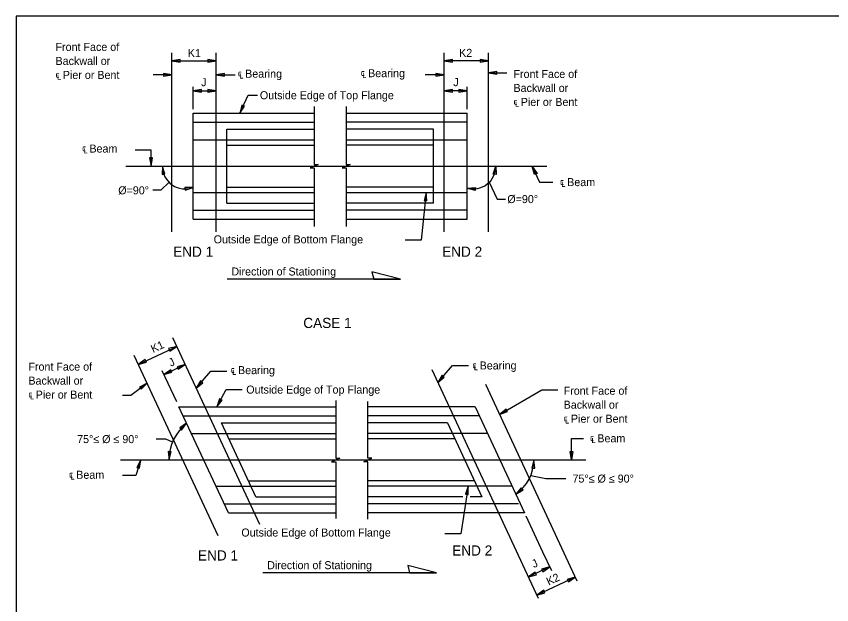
# Model space of a CAD drawing. Extents: x 120790.7 to 120844.8, y 120612.1 to 120653.6.
# Drawn here: x 120790.7 to 120806.1, y 120639.21 to 120650.31 of the extents above; entities that cross this region are included whole.
import ezdxf

# ---------------------------------------------------------------- set-up
doc = ezdxf.new("R2010")
doc.units = 0
for name, color, linetype in [('ActivePts-ConstElements', 7, 'Continuous'), ('AdhocPoint_dp', 7, 'Continuous'), ('Border', 7, 'Continuous'), ('Patterning', 7, 'Continuous'), ('PlotBorder_dp', 7, 'Continuous'), ('TextMisc', 7, 'Continuous')]:
    doc.layers.add(name, color=color, linetype=linetype)

# ---------------------------------------------------------------- blocks, each defined once
blk = doc.blocks.new('Terminator-Arrow')
at = {"layer": 'PlotBorder_dp'}
blk.add_lwpolyline([(0, 0), (-0.00041, 0.000069), (-0.00041, -0.000069)], close=True, dxfattribs=at)

msp = doc.modelspace()

# ---------------------------------------------------------------- linework, layer by layer
at = {"layer": 'ActivePts-ConstElements'}
msp.add_lwpolyline([(120790.703, 120630.851), (120821.491, 120630.851), (120821.491, 120650.31), (120790.703, 120650.31)], close=True, dxfattribs=at)
at = {"layer": 'AdhocPoint_dp'}
for p, q in [((120794.041, 120648.482), (120796.325, 120648.482)), ((120794.041, 120646.482), (120794.041, 120648.482)), ((120796.93, 120648.482), (120799.214, 120648.482)), ((120799.214, 120646.482), (120799.214, 120648.482)), ((120794.677, 120646.784), (120794.677, 120648.18)), ((120794.677, 120648.18), (120796.325, 120648.18)), ((120798.579, 120648.18), (120796.93, 120648.18)), ((120798.579, 120646.784), (120798.579, 120648.18)), ((120794.677, 120647.878), (120796.325, 120647.878)), ((120798.579, 120647.878), (120796.93, 120647.878)), ((120794.677, 120647.087), (120796.325, 120647.087)), ((120798.579, 120647.087), (120796.93, 120647.087)), ((120794.677, 120646.784), (120796.325, 120646.784)), ((120798.579, 120646.784), (120796.93, 120646.784)), ((120794.041, 120646.482), (120796.325, 120646.482)), ((120796.93, 120646.482), (120799.214, 120646.482)), ((120794.707, 120640.942), (120793.774, 120642.942)), ((120793.774, 120642.942), (120796.733, 120642.942)), ((120799.365, 120642.942), (120797.338, 120642.942)), ((120799.365, 120642.942), (120800.297, 120640.942)), ((120794.577, 120642.641), (120796.733, 120642.641)), ((120795.228, 120641.244), (120794.577, 120642.641)), ((120798.843, 120642.641), (120797.338, 120642.641)), ((120798.843, 120642.641), (120799.494, 120641.244)), ((120794.718, 120642.338), (120796.733, 120642.338)), ((120798.984, 120642.338), (120797.338, 120642.338)), ((120795.087, 120641.547), (120796.733, 120641.547)), ((120799.353, 120641.547), (120797.338, 120641.547)), ((120795.228, 120641.244), (120796.733, 120641.244)), ((120799.134, 120641.244), (120797.338, 120641.244)), ((120799.494, 120641.244), (120799.269, 120641.244)), ((120794.707, 120640.942), (120796.733, 120640.942)), ((120800.297, 120640.942), (120797.338, 120640.942))]:
    msp.add_line(p, q, dxfattribs=at)
at = {"layer": 'Border'}
for p, q in [((120794.041, 120648.313), (120796.325, 120648.313)), ((120799.214, 120648.313), (120796.93, 120648.313)), ((120794.041, 120647.978), (120796.325, 120647.978)), ((120796.93, 120647.978), (120799.214, 120647.978)), ((120794.041, 120646.987), (120796.325, 120646.987)), ((120796.93, 120646.987), (120799.214, 120646.987)), ((120794.041, 120646.652), (120796.325, 120646.652)), ((120799.214, 120646.652), (120796.93, 120646.652)), ((120793.853, 120642.773), (120796.733, 120642.773)), ((120799.444, 120642.773), (120797.338, 120642.773)), ((120794.01, 120642.438), (120796.733, 120642.438)), ((120799.6, 120642.438), (120797.338, 120642.438)), ((120794.472, 120641.447), (120796.733, 120641.447)), ((120800.062, 120641.447), (120797.338, 120641.447)), ((120794.628, 120641.112), (120796.733, 120641.112)), ((120800.181, 120641.112), (120797.338, 120641.112))]:
    msp.add_line(p, q, dxfattribs=at)
at = {"layer": 'Patterning'}
for points in [[(120797.417, 120645.493), (120797.452, 120645.349), (120797.959, 120645.349)], [(120798.093, 120639.953), (120798.129, 120639.809), (120798.636, 120639.809)]]:
    msp.add_lwpolyline(points, close=True, dxfattribs=at)
at = {"layer": 'PlotBorder_dp'}
for p, q in [((120793.639, 120649.469), (120794.477, 120649.469)), ((120793.639, 120649.469), (120794.477, 120649.469)), ((120799.617, 120649.469), (120798.779, 120649.469)), ((120799.617, 120649.469), (120798.779, 120649.469)), ((120793.639, 120649.208), (120793.289, 120649.206)), ((120793.639, 120649.208), (120793.289, 120649.206)), ((120794.477, 120649.206), (120794.529, 120649.206)), ((120794.477, 120649.206), (120794.529, 120649.206)), ((120794.529, 120649.206), (120794.832, 120649.206)), ((120794.529, 120649.206), (120794.832, 120649.206)), ((120798.726, 120649.206), (120798.423, 120649.206)), ((120798.726, 120649.206), (120798.423, 120649.206)), ((120799.617, 120649.245), (120799.966, 120649.242)), ((120799.617, 120649.245), (120799.966, 120649.242)), ((120794.041, 120648.558), (120794.041, 120648.979)), ((120794.041, 120648.558), (120794.041, 120648.979)), ((120794.041, 120648.903), (120794.477, 120648.903)), ((120794.041, 120648.903), (120794.477, 120648.903)), ((120799.214, 120648.903), (120798.779, 120648.903)), ((120799.214, 120648.903), (120798.779, 120648.903)), ((120799.214, 120648.558), (120799.214, 120648.979)), ((120799.214, 120648.558), (120799.214, 120648.979)), ((120794.921, 120648.482), (120795.08, 120648.824)), ((120794.921, 120648.482), (120795.08, 120648.824)), ((120795.08, 120648.824), (120795.254, 120648.824)), ((120795.08, 120648.824), (120795.254, 120648.824)), ((120793.246, 120647.784), (120792.944, 120647.784)), ((120793.246, 120647.784), (120792.944, 120647.784)), ((120793.246, 120647.482), (120793.246, 120647.784)), ((120793.246, 120647.482), (120793.246, 120647.784)), ((120798.443, 120646.987), (120798.345, 120646.085)), ((120798.443, 120646.987), (120798.345, 120646.085)), ((120798.345, 120646.085), (120798.043, 120646.085)), ((120798.345, 120646.085), (120798.043, 120646.085)), ((120797.959, 120645.349), (120794.684, 120645.349)), ((120793.006, 120643.745), (120793.732, 120644.083)), ((120793.006, 120643.745), (120793.732, 120644.083)), ((120793.489, 120643.553), (120793.892, 120643.741)), ((120793.489, 120643.553), (120793.892, 120643.741)), ((120798.659, 120643.403), (120798.937, 120643.72)), ((120798.659, 120643.403), (120798.937, 120643.72)), ((120798.937, 120643.72), (120799.24, 120643.72)), ((120798.937, 120643.72), (120799.24, 120643.72)), ((120793.731, 120643.036), (120793.458, 120643.622)), ((120793.731, 120643.036), (120793.458, 120643.622)), ((120794.099, 120643.297), (120794.377, 120643.614)), ((120794.099, 120643.297), (120794.377, 120643.614)), ((120794.377, 120643.614), (120794.679, 120643.614)), ((120794.377, 120643.614), (120794.679, 120643.614)), ((120793.171, 120643.39), (120792.863, 120643.158)), ((120793.171, 120643.39), (120792.863, 120643.158)), ((120794.491, 120642.942), (120794.664, 120643.272)), ((120794.491, 120642.942), (120794.664, 120643.272)), ((120794.664, 120643.272), (120794.967, 120643.272)), ((120794.664, 120643.272), (120794.967, 120643.272)), ((120799.827, 120642.796), (120800.622, 120643.266)), ((120799.827, 120642.796), (120800.622, 120643.266)), ((120800.622, 120643.266), (120800.925, 120643.266)), ((120800.622, 120643.266), (120800.925, 120643.266)), ((120792.863, 120643.158), (120792.71, 120643.158)), ((120792.863, 120643.158), (120792.71, 120643.158)), ((120801.183, 120641.942), (120801.185, 120642.345)), ((120801.183, 120641.942), (120801.185, 120642.345)), ((120801.185, 120642.345), (120801.408, 120642.345)), ((120801.185, 120642.345), (120801.408, 120642.345)), ((120793.051, 120641.942), (120792.961, 120641.645)), ((120793.051, 120641.942), (120792.961, 120641.645)), ((120792.961, 120641.645), (120792.71, 120641.645)), ((120792.961, 120641.645), (120792.71, 120641.645)), ((120799.234, 120641.447), (120799.093, 120640.549)), ((120799.234, 120641.447), (120799.093, 120640.549)), ((120800.324, 120640.885), (120800.639, 120640.209)), ((120800.324, 120640.885), (120800.639, 120640.209)), ((120799.093, 120640.549), (120798.79, 120640.549)), ((120799.093, 120640.549), (120798.79, 120640.549)), ((120800.639, 120640.209), (120800.805, 120639.854)), ((120800.639, 120640.209), (120800.805, 120639.854)), ((120798.636, 120639.809), (120795.36, 120639.809)), ((120800.773, 120639.923), (120800.37, 120639.735)), ((120800.773, 120639.923), (120800.37, 120639.735)), ((120801.256, 120639.731), (120800.53, 120639.393)), ((120801.256, 120639.731), (120800.53, 120639.393))]:
    msp.add_line(p, q, dxfattribs=at)
for points in [[(120796.325, 120648.612), (120796.325, 120647.516), (120796.403, 120647.516), (120796.248, 120647.449), (120796.325, 120647.449), (120796.325, 120646.346)], [(120796.325, 120648.612), (120796.325, 120647.516), (120796.403, 120647.516), (120796.248, 120647.449), (120796.325, 120647.449), (120796.325, 120646.346)], [(120796.93, 120648.612), (120796.93, 120647.516), (120797.007, 120647.516), (120796.852, 120647.449), (120796.93, 120647.449), (120796.93, 120646.346)], [(120796.93, 120648.612), (120796.93, 120647.516), (120797.007, 120647.516), (120796.852, 120647.449), (120796.93, 120647.449), (120796.93, 120646.346)], [(120800.443, 120647.477), (120800.583, 120647.183), (120800.834, 120647.183)], [(120800.443, 120647.477), (120800.583, 120647.183), (120800.834, 120647.183)], [(120793.586, 120647.179), (120793.434, 120647.028), (120793.281, 120647.028)], [(120799.63, 120647.179), (120799.782, 120646.858), (120799.936, 120646.858)], [(120799.63, 120647.179), (120799.782, 120646.858), (120799.936, 120646.858)], [(120796.733, 120643.06), (120796.733, 120641.976), (120796.811, 120641.976), (120796.656, 120641.909), (120796.733, 120641.909), (120796.733, 120640.839)], [(120796.733, 120643.06), (120796.733, 120641.976), (120796.811, 120641.976), (120796.656, 120641.909), (120796.733, 120641.909), (120796.733, 120640.839)], [(120797.338, 120640.825), (120797.338, 120641.909), (120797.261, 120641.909), (120797.416, 120641.976), (120797.338, 120641.976), (120797.338, 120643.045)], [(120797.338, 120640.825), (120797.338, 120641.909), (120797.261, 120641.909), (120797.416, 120641.976), (120797.338, 120641.976), (120797.338, 120643.045)], [(120793.653, 120642.28), (120793.523, 120642.334), (120793.344, 120642.334)], [(120793.653, 120642.28), (120793.523, 120642.334), (120793.344, 120642.334)], [(120800.416, 120641.646), (120800.702, 120641.592), (120800.77, 120641.592)], [(120800.416, 120641.646), (120800.702, 120641.592), (120801.075, 120641.592)]]:
    msp.add_lwpolyline(points, dxfattribs=at)
for points in [[(120793.461, 120647.482), (120793.457, 120647.324), (120793.509, 120647.332)], [(120799.756, 120647.482), (120799.76, 120647.324), (120799.707, 120647.332)], [(120800.443, 120647.477), (120800.535, 120647.348), (120800.487, 120647.325)], [(120800.443, 120647.477), (120800.535, 120647.348), (120800.487, 120647.325)], [(120794.041, 120647.082), (120793.883, 120647.082), (120793.891, 120647.03)], [(120799.214, 120647.069), (120799.372, 120647.079), (120799.367, 120647.027)], [(120793.918, 120642.633), (120793.787, 120642.545), (120793.824, 120642.506)], [(120793.586, 120641.942), (120793.624, 120642.096), (120793.571, 120642.1)], [(120800.475, 120641.942), (120800.437, 120641.789), (120800.49, 120641.785)], [(120800.131, 120641.299), (120800.269, 120641.377), (120800.236, 120641.418)]]:
    msp.add_lwpolyline(points, close=True, dxfattribs=at)
for centre, radius, start, end in [((120793.889, 120647.482), 0.429, 180, 290.7788), ((120799.327, 120647.482), 0.429, 254.6951, 0), ((120794.469, 120641.942), 0.884, 128.5493, 180), ((120799.7, 120641.942), 0.774, 303.7741, 0)]:
    msp.add_arc(centre, radius, start, end, dxfattribs=at)
at = {"layer": 'TextMisc'}
for p, q in [((120793.639, 120646.242), (120793.639, 120649.62)), ((120794.477, 120646.242), (120794.477, 120649.62)), ((120798.779, 120646.242), (120798.779, 120649.62)), ((120799.617, 120646.242), (120799.617, 120649.62)), ((120792.771, 120647.482), (120800.721, 120647.482)), ((120795.299, 120640.724), (120793.655, 120644.248)), ((120794.514, 120640.511), (120792.929, 120643.91)), ((120798.545, 120643.65), (120800.556, 120639.337)), ((120799.558, 120643.373), (120801.288, 120639.663)), ((120792.67, 120641.942), (120801.457, 120641.942))]:
    msp.add_line(p, q, dxfattribs=at)

# ---------------------------------------------------------------- block references
at = {"layer": 'PlotBorder_dp'}
for p, xscale, yscale, rotation in [((120793.639, 120649.469), 381, 384.0238095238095, 180), ((120793.639, 120649.469), 381, 384.0238095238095, 180), ((120798.779, 120649.469), 381, 384.0238095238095, 180), ((120798.779, 120649.469), 381, 384.0238095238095, 180), ((120793.639, 120649.208), 380.99999999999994, 384.02380952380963, 0.37716899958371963), ((120793.639, 120649.208), 380.99999999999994, 384.02380952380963, 0.37716899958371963), ((120794.477, 120649.206), 381.00000000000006, 384.0238095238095, -179.96491509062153), ((120794.477, 120649.206), 381.00000000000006, 384.0238095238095, -179.96491509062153), ((120798.779, 120649.206), 381, 384.0238095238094, -0.03510757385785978), ((120798.779, 120649.206), 381, 384.0238095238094, -0.03510757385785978), ((120799.617, 120649.245), 381, 384.0238095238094, 179.62286774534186), ((120799.617, 120649.245), 381, 384.0238095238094, 179.62286774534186), ((120794.041, 120648.903), 381, 384.0238095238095, 180), ((120794.041, 120648.903), 381, 384.0238095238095, 180), ((120798.779, 120648.903), 381, 384.0238095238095, 180), ((120798.779, 120648.903), 381, 384.0238095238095, 180), ((120794.921, 120648.482), 381, 384.0238095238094, -114.94557593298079), ((120794.921, 120648.482), 381, 384.0238095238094, -114.94557593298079), ((120793.246, 120647.482), 381, 384.0238095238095, -90), ((120793.246, 120647.482), 381, 384.0238095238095, -90), ((120798.443, 120646.987), 381, 384.0238095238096, 83.8251389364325), ((120798.443, 120646.987), 381, 384.0238095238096, 83.8251389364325), ((120793.732, 120644.083), 381, 384.0238095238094, 24.9944758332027), ((120793.732, 120644.083), 381, 384.0238095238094, 24.9944758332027), ((120793.006, 120643.745), 381, 384.0238095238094, -155.0055241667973), ((120793.006, 120643.745), 381, 384.0238095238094, -155.0055241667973), ((120793.489, 120643.553), 380.99999999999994, 384.0238095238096, -155.00552416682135), ((120793.489, 120643.553), 380.99999999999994, 384.0238095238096, -155.00552416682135), ((120793.892, 120643.741), 380.99999999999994, 384.0238095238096, 24.994475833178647), ((120793.892, 120643.741), 380.99999999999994, 384.0238095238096, 24.994475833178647), ((120798.659, 120643.403), 381, 384.0238095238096, -131.21941588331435), ((120798.659, 120643.403), 381, 384.0238095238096, -131.21941588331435), ((120793.171, 120643.39), 381, 384.0238095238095, 36.99205670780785), ((120793.171, 120643.39), 381, 384.0238095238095, 36.99205670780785), ((120794.099, 120643.297), 381, 384.0238095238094, -131.21867682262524), ((120794.099, 120643.297), 381, 384.0238095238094, -131.21867682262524), ((120794.491, 120642.942), 381, 384.0238095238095, -117.72534965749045), ((120794.491, 120642.942), 381, 384.0238095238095, -117.72534965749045), ((120799.827, 120642.796), 381.00000000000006, 384.0238095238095, -149.40161216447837), ((120799.827, 120642.796), 381.00000000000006, 384.0238095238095, -149.40161216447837), ((120793.051, 120641.942), 380.99999999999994, 384.0238095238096, 73.21326448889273), ((120793.051, 120641.942), 380.99999999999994, 384.0238095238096, 73.21326448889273), ((120801.183, 120641.942), 380.99999999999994, -384.02380952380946, -90.31997310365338), ((120801.183, 120641.942), 380.99999999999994, -384.02380952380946, -90.31997310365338), ((120799.234, 120641.447), 381, 384.0238095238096, 81.04426286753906), ((120799.234, 120641.447), 381, 384.0238095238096, 81.04426286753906), ((120800.773, 120639.923), 381, 384.0238095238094, 24.9944758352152), ((120800.773, 120639.923), 381, 384.0238095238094, 24.9944758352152), ((120800.37, 120639.735), 381, 384.0238095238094, -155.00552416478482), ((120800.37, 120639.735), 381, 384.0238095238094, -155.00552416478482), ((120801.256, 120639.731), 381, 384.0238095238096, 24.994475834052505), ((120801.256, 120639.731), 381, 384.0238095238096, 24.994475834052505), ((120800.53, 120639.393), 381, 384.0238095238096, -155.00552416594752), ((120800.53, 120639.393), 381, 384.0238095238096, -155.00552416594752)]:
    msp.add_blockref('Terminator-Arrow', p, dxfattribs=dict(at, xscale=xscale, yscale=yscale, rotation=rotation))
at = {"layer": 'PlotBorder_dp', "xscale": 381, "yscale": 384.0238095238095}
for p in [(120794.477, 120649.469), (120794.477, 120649.469), (120799.617, 120649.469), (120799.617, 120649.469), (120794.477, 120648.903), (120794.477, 120648.903), (120799.214, 120648.903), (120799.214, 120648.903)]:
    msp.add_blockref('Terminator-Arrow', p, dxfattribs=at)

# ---------------------------------------------------------------- texts
at = {"layer": 'Patterning'}
for s, height, p in [('K1', 0.1512, (120793.941, 120649.541)), ('K2', 0.1512, (120799.063, 120649.545)), ('℄ Bearing', 0.1512, (120794.885, 120649.152)), ('℄ Bearing', 0.1512, (120797.206, 120649.162)), ('J', 0.151, (120794.194, 120648.992)), ('J', 0.151, (120798.953, 120648.993)), ('Outside Edge of Top Flange', 0.1512, (120795.301, 120648.746)), ('℄ Beam', 0.1512, (120791.945, 120647.74)), ('℄ Beam', 0.1512, (120800.965, 120647.107)), ('Ø=90°', 0.1512, (120792.627, 120646.952)), ('Ø=90°', 0.1512, (120799.973, 120646.787)), ('Outside Edge of Bottom Flange', 0.1512, (120794.429, 120646.027)), ('END 1', 0.192, (120793.664, 120645.774)), ('END 2', 0.192, (120798.742, 120645.774)), ('Direction of Stationing', 0.1512, (120794.763, 120645.421)), ('CASE 1', 0.192, (120796.121, 120644.43)), ('℄ Bearing', 0.1512, (120799.312, 120643.648)), ('℄ Bearing', 0.1512, (120794.75, 120643.56)), ('℄ Bearing', 0.1512, (120794.75, 120643.56)), ('Outside Edge of Top Flange', 0.1512, (120795.044, 120643.193)), ('75°≤ Ø ≤ 90°', 0.1512, (120791.851, 120642.259)), ('℄ Beam', 0.1512, (120801.534, 120642.274)), ('℄ Beam', 0.1512, (120791.696, 120641.586)), ('75°≤ Ø ≤ 90°', 0.1512, (120801.203, 120641.514)), ('Outside Edge of Bottom Flange', 0.1512, (120794.951, 120640.497)), ('END 2', 0.192, (120798.932, 120640.137)), ('END 1', 0.192, (120794.133, 120640.044)), ('Direction of Stationing', 0.1512, (120795.439, 120639.881))]:
    msp.add_text(s, height=height, dxfattribs=at).set_placement(p)
for s, height, p in [('K1', 0.1512, (120793.285, 120643.958)), ('J', 0.151, (120793.62, 120643.697)), ('J', 0.151, (120800.475, 120639.9)), ('K2', 0.1512, (120800.753, 120639.57))]:
    msp.add_text(s, height=height, rotation=24.9945, dxfattribs=at).set_placement(p)
at = {"layer": 'PlotBorder_dp'}
for s, p in [('Front Face of', (120791.443, 120649.657)), ('Backwall or', (120791.443, 120649.393)), ('℄ Pier or Bent', (120791.443, 120649.129)), ('Front Face of', (120800.089, 120649.147)), ('Backwall or', (120800.089, 120648.883)), ('℄ Pier or Bent', (120800.089, 120648.619)), ('Front Face of', (120790.931, 120643.626)), ('Backwall or', (120790.931, 120643.362)), ('Front Face of', (120801.036, 120643.172)), ('℄ Pier or Bent', (120790.931, 120643.098)), ('Backwall or', (120801.036, 120642.908)), ('℄ Pier or Bent', (120801.036, 120642.644))]:
    msp.add_text(s, height=0.1512, dxfattribs=at).set_placement(p)

doc.saveas('drawing.dxf')
